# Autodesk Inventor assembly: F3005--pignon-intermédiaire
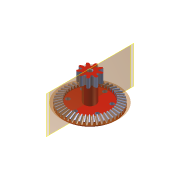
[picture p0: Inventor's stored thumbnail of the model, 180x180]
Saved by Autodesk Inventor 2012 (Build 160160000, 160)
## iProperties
Created: 2014-12
Part Number: F3005--pignon-intermédiaire
Document SubType Name: Assembly
Designer: Bruno
Mass: 7.28562 g
Surface Area: 60.9595 cm^2
Volume: 7.28562 cm^3
Density: 1 g/cm^3
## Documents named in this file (3)
- F:\Systèmes\secateur-hydrogene-Pragma\Documentation\Dossier technique Infaco F3005\Solidworks\Composants importés\F3005--pignon-intermédiaire.iam
- F:\Systèmes\secateur-hydrogene-Pragma\Documentation\Dossier technique Infaco F3005\Solidworks\Composants importés\F3005\Couronne.ipt
- F:\Systèmes\secateur-hydrogene-Pragma\Documentation\Dossier technique Infaco F3005\Solidworks\Composants importés\F3005\Pignon 9dts.ipt
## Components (2 placed, 2 different names)
1. Couronne:1
2. Pignon 9dts:1
